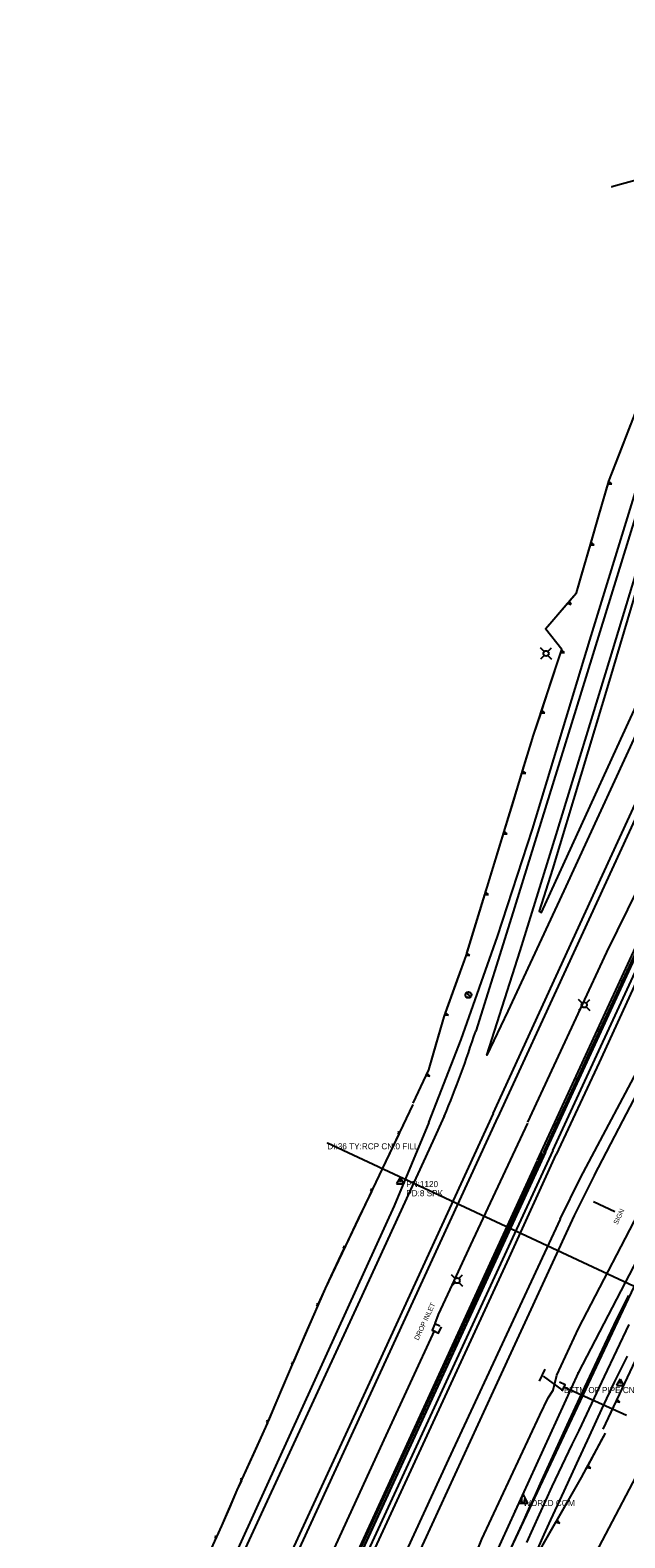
# Model space of a CAD drawing. Extents: x 978516 to 993312, y 1836504 to 1846212.
# Drawn here: x 980417 to 980904, y 1840451 to 1841686 of the extents above; entities that cross this region are included whole.
import ezdxf

# ---------------------------------------------------------------- set-up
doc = ezdxf.new("R2010")
doc.units = 0
for name, color, linetype in [('R_MOT Stage 1 Widening', 7, 'Continuous'), ('S_BASELINE', 7, 'Continuous'), ('S_CROSS_DRAIN', 7, 'Continuous'), ('S_CROSS_DRAIN_ANNOT', 7, 'Continuous'), ('S_DRG_PT_SYM', 7, 'Continuous'), ('S_DROP_INLET', 7, 'Continuous'), ('S_DROP_INLET_ANNOT', 7, 'Continuous'), ('S_EDGE_PAVEMENT', 7, 'Continuous'), ('S_FENCE', 7, 'Continuous'), ('S_HEADWALL', 7, 'Continuous'), ('S_MISC_STRUCTURES', 7, 'Continuous'), ('S_PAVEMENT_CROWN', 7, 'Continuous'), ('S_SANITARY_SEWER', 7, 'Continuous'), ('S_SECONDARY_CTL', 7, 'Continuous'), ('S_SECONDARY_CTL_ANNOT', 7, 'Continuous'), ('S_SHOULDER', 7, 'Continuous'), ('S_SIGN', 7, 'Continuous'), ('S_SIGN_ANNOT', 7, 'Continuous'), ('S_STREAM', 7, 'Continuous'), ('S_TREE', 7, 'Continuous'), ('S_UNDERGROUND_CABLE', 7, 'Continuous'), ('S_UTILITY_POLE', 7, 'Continuous'), ('S_UTILITY_POLE_ANNOT', 7, 'Continuous'), ('S_UTL_PT_SYM', 7, 'Continuous')]:
    doc.layers.add(name, color=color, linetype=linetype)

msp = doc.modelspace()

# ---------------------------------------------------------------- linework, layer by layer
at = {"layer": 'R_MOT Stage 1 Widening'}
msp.add_line((981449.8, 1841520.7), (980710.3, 1840116.9), dxfattribs=at)
at = {"layer": 'S_BASELINE'}
msp.add_line((980563.3, 1839916.3), (980929, 1840693.9), dxfattribs=at)
at = {"layer": 'S_CROSS_DRAIN'}
for p, q in [((981670.3, 1841767.9), (980893.4, 1841557.7)), ((981010.9, 1840610.6), (980660.5, 1840774.4)), ((980905.5, 1840551.6), (980854.1, 1840574.8))]:
    msp.add_line(p, q, dxfattribs=at)
at = {"layer": 'S_DRG_PT_SYM'}
for points in [[(980893.4, 1841557.7), (980893.4, 1841557.7), (980893.4, 1841557.7), (980893.4, 1841557.7), (980893.4, 1841557.7), (980893.4, 1841557.6), (980893.4, 1841557.7), (980893.5, 1841557.7)], [(980660.5, 1840774.4), (980660.5, 1840774.5), (980660.5, 1840774.4), (980660.5, 1840774.4), (980660.5, 1840774.4), (980660.5, 1840774.4), (980660.5, 1840774.4), (980660.6, 1840774.4)], [(980854.1, 1840574.8), (980854.1, 1840574.9), (980854.1, 1840574.8), (980854, 1840574.8), (980854.1, 1840574.8), (980854.1, 1840574.8), (980854.1, 1840574.8), (980854.1, 1840574.8)]]:
    msp.add_lwpolyline(points, dxfattribs=at)
at = {"layer": 'S_DROP_INLET'}
msp.add_lwpolyline([(980752.6, 1840624.6), (980748.6, 1840626.4), (980746.3, 1840621.4), (980751.5, 1840618.9), (980753.8, 1840624.1)], dxfattribs=at)
at = {"layer": 'S_EDGE_PAVEMENT'}
for points in [[(981003.8, 1841586), (980971.6, 1841480.7), (980921.6, 1841316.8), (980863.8, 1841129.5), (980811.1, 1840959.6), (980782, 1840866.2)], [(981106.5, 1841528.7), (981088, 1841488.6), (981015.6, 1841331.7), (980924.3, 1841133.4), (980854.2, 1840981), (980808.2, 1840882.6), (980791.1, 1840846.5), (980818.4, 1840932), (980847.7, 1841026.9), (980892.4, 1841172.2), (980941.7, 1841334.9), (981014.4, 1841572.8)], [(980796.3, 1840798.9), (980885.8, 1840994), (980983.5, 1841206.2), (981066.6, 1841386.4), (981127.4, 1841517.9)], [(981184.7, 1841496.4), (981112.4, 1841339.5), (981025.6, 1841150.3), (980952.7, 1840992.2), (980883, 1840840.4), (980847.7, 1840765.2)], [(980851.2, 1840712.3), (980867.8, 1840746.2), (980923.2, 1840850.4), (980998.5, 1840980.7), (981063.5, 1841091.8), (981158.1, 1841253.2), (981246.3, 1841402.8), (981274, 1841449.9)], [(980796.3, 1840798.9), (980696.5, 1840582), (980575.8, 1840319.9), (980465.8, 1840080)], [(980426.4, 1840071.6), (980466.2, 1840166.9), (980544, 1840335.5), (980687.3, 1840645.9), (980747.1, 1840776), (980756.3, 1840796.5)], [(980518.1, 1840050.1), (980634.6, 1840302.1), (980711, 1840467.7), (980809.2, 1840680.7), (980847.7, 1840765.2)], [(980851.2, 1840712.3), (980759.6, 1840515.7), (980663.5, 1840307), (980582.4, 1840130.9), (980540.6, 1840039.6)], [(980805.3, 1840430.6), (980814.9, 1840451.4), (980820.2, 1840463.1), (980825.5, 1840474.9), (980830.8, 1840486.6), (980836.1, 1840498.3), (980846.4, 1840520.9), (980856.8, 1840543.5), (980867.1, 1840565.8), (980877.5, 1840588.1), (980887.7, 1840609.5), (980897.8, 1840630.9), (980907.2, 1840649.6)], [(980832.7, 1840442.2), (980838.1, 1840454), (980843.5, 1840465.9), (980848.9, 1840477.7), (980854.3, 1840489.5), (980864.7, 1840512.1), (980875.1, 1840534.6), (980885.3, 1840556.7), (980895.6, 1840578.8), (980906.1, 1840600.1)]]:
    msp.add_lwpolyline(points, dxfattribs=at)
msp.add_ellipse((980562.9, 1840901.9), major_axis=(162.8, 433.1), ratio=0.472367, start_param=4.646, end_param=4.806827, dxfattribs=at)
at = {"layer": 'S_FENCE'}
for p, q in [((980900.7, 1840905.3), (980902.9, 1840907.4)), ((980901.7, 1840904.8), (980901.9, 1840907.9)), ((980882.2, 1840865.4), (980884.4, 1840867.5)), ((980883.2, 1840864.9), (980883.4, 1840868)), ((980863.8, 1840825.4), (980866, 1840827.5)), ((980864.8, 1840824.9), (980865, 1840828)), ((980845.4, 1840785.5), (980847.6, 1840787.6)), ((980846.4, 1840784.9), (980846.6, 1840788.1)), ((980819.2, 1840728.1), (980820.6, 1840730.6)), ((980819.4, 1840728), (980820.4, 1840730.7)), ((980800.8, 1840688.2), (980802.2, 1840690.6)), ((980801, 1840688), (980802, 1840690.8)), ((980782.3, 1840648.2), (980783.7, 1840650.7)), ((980782.5, 1840648.1), (980783.5, 1840650.8)), ((980763.9, 1840608.3), (980765.3, 1840610.7)), ((980764.1, 1840608.1), (980765.1, 1840610.9)), ((980745.5, 1840568.3), (980746.9, 1840570.8)), ((980745.7, 1840568.2), (980746.7, 1840570.9)), ((980727, 1840528.4), (980728.4, 1840530.8)), ((980727.2, 1840528.2), (980728.2, 1840531)), ((980708.6, 1840488.4), (980710, 1840490.9)), ((980708.8, 1840488.3), (980709.8, 1840491))]:
    msp.add_line(p, q, dxfattribs=at)
for points in [[(980837.3, 1840766.5), (980949, 1841008.8), (981030.5, 1841186.7), (981097.8, 1841332.7), (981154.5, 1841455.6)], [(980902.6, 1840908.2), (980911, 1840926.4)], [(980892.6, 1840886.4), (980900.9, 1840904.6)], [(980884.2, 1840868.2), (980892.6, 1840886.4)], [(980874.1, 1840846.4), (980882.5, 1840864.6)], [(980865.8, 1840828.3), (980874.1, 1840846.4)], [(980855.7, 1840806.5), (980864.1, 1840824.7)], [(980847.3, 1840788.3), (980855.7, 1840806.5)], [(980837.3, 1840766.5), (980845.6, 1840784.7)], [(980497.5, 1840030), (980690.5, 1840448.9), (980837, 1840766.4)], [(980829.1, 1840749.3), (980837, 1840766.4)], [(980820.8, 1840731.2), (980829.1, 1840749.3)], [(980810.7, 1840709.4), (980819.1, 1840727.5)], [(980802.3, 1840691.2), (980810.7, 1840709.4)], [(980792.3, 1840669.4), (980800.6, 1840687.6)], [(980783.9, 1840651.3), (980792.3, 1840669.4)], [(980773.8, 1840629.5), (980782.2, 1840647.6)], [(980765.4, 1840611.3), (980773.8, 1840629.5)], [(980755.4, 1840589.5), (980763.8, 1840607.7)], [(980747, 1840571.4), (980755.4, 1840589.5)], [(980737, 1840549.6), (980745.3, 1840567.7)], [(980728.6, 1840531.4), (980737, 1840549.6)], [(980718.5, 1840509.6), (980726.9, 1840527.8)], [(980710.1, 1840491.5), (980718.5, 1840509.6)], [(980700.1, 1840469.7), (980708.5, 1840487.8)], [(980691.7, 1840451.5), (980700.1, 1840469.7)]]:
    msp.add_lwpolyline(points, dxfattribs=at)
at = {"layer": 'S_HEADWALL'}
for points in [[(980834.1, 1840579.5), (980838.7, 1840589.4)], [(980852.8, 1840571.4), (980855.1, 1840576.6), (980850.5, 1840578.8)]]:
    msp.add_lwpolyline(points, dxfattribs=at)
at = {"layer": 'S_MISC_STRUCTURES'}
for points in [[(980839.1, 1840767.1), (981003, 1841122.8), (981098.1, 1841329.4), (981134.4, 1841407.3), (981157.1, 1841455.3), (981153.1, 1841457.4), (981097.5, 1841337), (981013.7, 1841154), (980881.3, 1840867.3), (980832.3, 1840760.5)], [(980832.2, 1840760.3), (980652.9, 1840370), (980494.9, 1840028.6)], [(980500.9, 1840033.1), (980708.6, 1840483.5), (980839.1, 1840767.1), (980839, 1840767.1), (980647, 1840349.4), (980499.2, 1840029.2)]]:
    msp.add_lwpolyline(points, dxfattribs=at)
at = {"layer": 'S_PAVEMENT_CROWN'}
msp.add_lwpolyline([(980823.9, 1840447.6), (980829.1, 1840459), (980834.2, 1840470.5), (980839.4, 1840481.9), (980844.5, 1840493.4), (980850, 1840504.8), (980855.5, 1840516.2), (980861, 1840527.6), (980866.5, 1840539.1), (980876.9, 1840561.3), (980887.3, 1840583.5), (980897.4, 1840604.8), (980907.6, 1840626.1)], dxfattribs=at)
at = {"layer": 'S_SANITARY_SEWER'}
for p, q in [((980949.2, 1840747.1), (980865.8, 1840586.5)), ((980865.8, 1840586.5), (980814.1, 1840473.3)), ((980814.1, 1840473.3), (980730.7, 1840290.2))]:
    msp.add_line(p, q, dxfattribs=at)
at = {"layer": 'S_SECONDARY_CTL'}
for p, q in [((980720.1, 1840746.1), (980717.1, 1840741.2)), ((980717.1, 1840741.2), (980723, 1840741.2)), ((980720.1, 1840746.1), (980723, 1840741.2)), ((980900.1, 1840581.1), (980897.1, 1840576.1)), ((980897.1, 1840576.1), (980903, 1840576.1)), ((980900.1, 1840581.1), (980903, 1840576.1))]:
    msp.add_line(p, q, dxfattribs=at)
for centre, radius in [((980720.1, 1840743.5), 0.311), ((980720.1, 1840743.5), 0.183), ((980720.1, 1840743.5), 0.103), ((980900.1, 1840578.5), 0.311), ((980900.1, 1840578.5), 0.183), ((980900.1, 1840578.5), 0.103)]:
    msp.add_circle(centre, radius, dxfattribs=at)
at = {"layer": 'S_SHOULDER'}
for points in [[(981020.1, 1841576.9), (980960.7, 1841383.6), (980935.5, 1841301.6), (980891.2, 1841152.8), (980844.7, 1840998.9), (980833.9, 1840964.4), (980835.7, 1840963.5), (980900.8, 1841105.2), (980961, 1841236.4), (981052.1, 1841434.2), (981098.7, 1841534.3)], [(980743.6, 1840791.3), (980770.1, 1840859.3), (980799.9, 1840943.6), (980828.4, 1841031.5), (980875.3, 1841186.3), (980935.8, 1841383.1), (980982.7, 1841537.3)], [(981133, 1841518.8), (981021.6, 1841276.6), (980931.1, 1841080.4), (980857.4, 1840920.2), (980799.8, 1840795.3)], [(980845.2, 1840768.5), (980928.9, 1840949.9), (981026.5, 1841161.7), (981122.3, 1841369.8), (981172.2, 1841479.4)], [(981279.6, 1841447.9), (981085.8, 1841116), (980988.3, 1840949), (980938, 1840861.5), (980902.1, 1840792.8), (980878.9, 1840748.3)], [(980743.6, 1840791.3), (980715.2, 1840723.1), (980668.5, 1840620.9), (980580.1, 1840426.8), (980489.8, 1840231.2), (980455.2, 1840155.4), (980417.2, 1840072.8)], [(980468.8, 1840075.4), (980639.4, 1840446.1), (980752.8, 1840692.8), (980800.2, 1840796)], [(980845.2, 1840768.5), (980731.5, 1840522.4), (980574.1, 1840181.3), (980513.8, 1840051.2)], [(980548.5, 1840031.9), (980677.2, 1840312), (980796.5, 1840571.3), (980862.9, 1840715.2), (980879.6, 1840749)]]:
    msp.add_lwpolyline(points, dxfattribs=at)
at = {"layer": 'S_SIGN'}
msp.add_lwpolyline([(980895.8, 1840718.3), (980878.3, 1840726.4)], dxfattribs=at)
msp.add_circle((980776, 1840895.9), 2.49, dxfattribs=at)
for centre, radius, start, end in [((980776.1, 1840897.1), 0.95, 16.5258, 156.8957), ((980776.7, 1840897.2), 1.5, 167.1196, 241.9813), ((980775.6, 1840894.5), 1.4, 358.6529, 73.7063), ((980775.9, 1840895), 1.28, 204.641, 335.359)]:
    msp.add_arc(centre, radius, start, end, dxfattribs=at)
at = {"layer": 'S_STREAM'}
for points in [[(980824.7, 1840791.7), (980889.3, 1840930.9), (980915.2, 1840983.7)], [(980824.3, 1840790.8), (980777.8, 1840691.2), (980760.8, 1840654.6), (980751.2, 1840634.1), (980748.5, 1840626.8)], [(980705.2, 1840264.9), (980744.1, 1840346.6), (980773.3, 1840415.8), (980787, 1840450.1), (980834.4, 1840551.8), (980841.2, 1840566), (980845.4, 1840572.2), (980848.3, 1840584.4), (980866, 1840622.6), (980922, 1840730.3)], [(980748.3, 1840621.3), (980708.5, 1840535), (980664.4, 1840439.2), (980626.5, 1840357.9), (980577.4, 1840252.8), (980527.9, 1840140.9), (980451.4, 1839975.2)], [(980837.2, 1840583.8), (980852.4, 1840572.5)]]:
    msp.add_lwpolyline(points, dxfattribs=at)
at = {"layer": 'S_TREE'}
for p, q in [((980893.4, 1841314.5), (980890.9, 1841316.3)), ((980890.3, 1841314.4), (980893.4, 1841314.5)), ((980878.9, 1841264.5), (980876.4, 1841266.4)), ((980875.8, 1841264.5), (980878.9, 1841264.5)), ((980857.2, 1841216.8), (980860.1, 1841215.6)), ((980860.1, 1841215.6), (980858.5, 1841218.3)), ((980851.6, 1841176.3), (980854.7, 1841176.3)), ((980854.7, 1841176.3), (980852.2, 1841178.2)), ((980835.4, 1841126.9), (980838.5, 1841126.9)), ((980838.5, 1841126.9), (980836, 1841128.8)), ((980819.8, 1841077.4), (980822.9, 1841077.4)), ((980822.9, 1841077.4), (980820.3, 1841079.3)), ((980804.6, 1841027.7), (980807.7, 1841027.8)), ((980807.7, 1841027.8), (980805.1, 1841029.6)), ((980789.3, 1840978), (980792.4, 1840978.1)), ((980792.4, 1840978.1), (980789.9, 1840979.9)), ((980774.1, 1840928.4), (980777.2, 1840928.4)), ((980777.2, 1840928.4), (980774.6, 1840930.2)), ((980756.5, 1840879.5), (980759.6, 1840879.4)), ((980759.6, 1840879.4), (980757.2, 1840881.3)), ((980741.4, 1840829.8), (980744.5, 1840829.4)), ((980744.5, 1840829.4), (980742.2, 1840831.6)), ((980719.8, 1840783.7), (980718.3, 1840783.3)), ((980718.3, 1840783.3), (980718.9, 1840781.9)), ((980697.4, 1840736.8), (980695.9, 1840736.4)), ((980695.9, 1840736.4), (980696.5, 1840735)), ((980675, 1840689.9), (980673.5, 1840689.5)), ((980673.5, 1840689.5), (980674.1, 1840688.1)), ((980653.1, 1840642.8), (980651.6, 1840642.3)), ((980651.6, 1840642.3), (980652.3, 1840641)), ((980632.6, 1840595), (980631.1, 1840594.6)), ((980631.1, 1840594.6), (980631.8, 1840593.2)), ((980896.9, 1840562.9), (980900, 1840562.5)), ((980900, 1840562.5), (980897.7, 1840564.7)), ((980612.2, 1840547.3), (980610.7, 1840546.8)), ((980610.7, 1840546.8), (980611.4, 1840545.4)), ((980873, 1840508.9), (980876.1, 1840508.3)), ((980876.1, 1840508.3), (980874, 1840510.6)), ((980590.9, 1840499.9), (980589.4, 1840499.4)), ((980589.4, 1840499.4), (980590.1, 1840498.1)), ((980847.6, 1840464.1), (980850.7, 1840463.4)), ((980850.7, 1840463.4), (980848.6, 1840465.8)), ((980569.9, 1840452.6), (980568.4, 1840452.1)), ((980568.4, 1840452.1), (980569.1, 1840450.8))]:
    msp.add_line(p, q, dxfattribs=at)
for points in [[(980730.7, 1840807.2), (980743.5, 1840834.4), (980756, 1840878), (980774, 1840928), (980791.2, 1840984.2), (980829.3, 1841108.5), (980852.4, 1841178.7), (980839, 1841195.6), (980864.4, 1841225.2), (980890.9, 1841316.5), (980928.7, 1841414.1), (980957.3, 1841511.3), (980972, 1841558.3)], [(980899.9, 1841339.6), (980908.9, 1841362.9)], [(980890.9, 1841316.3), (980890.9, 1841316.5), (980899.9, 1841339.6)], [(980883.3, 1841290.4), (980890.3, 1841314.4)], [(980876.4, 1841266.4), (980883.3, 1841290.4)], [(980868.9, 1841240.5), (980875.8, 1841264.5)], [(980858.5, 1841218.3), (980864.4, 1841225.2), (980868.9, 1841240.5)], [(980840.9, 1841197.8), (980857.2, 1841216.8)], [(980852.2, 1841178.2), (980852.4, 1841178.7), (980839, 1841195.6), (980840.9, 1841197.8)], [(980843.8, 1841152.6), (980851.6, 1841176.3)], [(980836, 1841128.8), (980843.8, 1841152.6)], [(980827.7, 1841103.2), (980829.3, 1841108.5), (980835.4, 1841126.9)], [(980820.3, 1841079.3), (980827.7, 1841103.2)], [(980812.5, 1841053.5), (980819.8, 1841077.4)], [(980805.1, 1841029.6), (980812.5, 1841053.5)], [(980797.2, 1841003.8), (980804.6, 1841027.7)], [(980789.9, 1840979.9), (980791.2, 1840984.2), (980797.2, 1841003.8)], [(980886.2, 1840540.3), (980961.4, 1840699.8), (980994.3, 1840749.1), (981040, 1840829.6), (981098.3, 1840928.6), (981121.2, 1840967.9), (981130.5, 1840975.5), (981171.8, 1840993.3), (981172, 1840993.4)], [(980782, 1840954.1), (980789.3, 1840978)], [(980774.6, 1840930.2), (980782, 1840954.1)], [(980765.6, 1840904.8), (980774, 1840928), (980774.1, 1840928.4)], [(980757.2, 1840881.3), (980765.6, 1840904.8)], [(980749.5, 1840855.5), (980756, 1840878), (980756.5, 1840879.5)], [(980742.2, 1840831.6), (980743.5, 1840834.4), (980749.5, 1840855.5)], [(980730.7, 1840807.2), (980741.4, 1840829.8)], [(980730.6, 1840806.2), (980658.6, 1840655.6), (980632.3, 1840594.6), (980609.9, 1840541.9), (980586.5, 1840490.2), (980573.8, 1840461.1), (980543, 1840393.4), (980524.3, 1840353.4), (980499.7, 1840298.6), (980480.4, 1840239.8)], [(980730.6, 1840806.2), (980719.8, 1840783.7)], [(980718.9, 1840781.9), (980708.2, 1840759.3)], [(980708.2, 1840759.3), (980697.4, 1840736.8)], [(980696.5, 1840735), (980685.8, 1840712.4)], [(980685.8, 1840712.4), (980675, 1840689.9)], [(980674.1, 1840688.1), (980663.3, 1840665.6)], [(980663.3, 1840665.6), (980658.6, 1840655.6), (980653.1, 1840642.8)], [(980652.3, 1840641), (980642.4, 1840618)], [(980642.4, 1840618), (980632.6, 1840595)], [(980631.8, 1840593.2), (980622, 1840570.2)], [(980897.7, 1840564.7), (980908.3, 1840587.2)], [(980622, 1840570.2), (980612.2, 1840547.3)], [(980886.2, 1840540.3), (980896.9, 1840562.9)], [(980611.4, 1840545.4), (980609.9, 1840541.9), (980601.2, 1840522.6)], [(980822.8, 1840330.6), (980809.5, 1840333.2), (980797.2, 1840340.9), (980796.7, 1840364.2), (980807.9, 1840389.2), (980822.1, 1840419.7), (980868.6, 1840500.7), (980888.3, 1840537.1)], [(980874, 1840510.6), (980885.5, 1840532)], [(980885.5, 1840532), (980888.3, 1840537.1)], [(980601.2, 1840522.6), (980590.9, 1840499.9)], [(980861, 1840487.4), (980868.6, 1840500.7), (980873, 1840508.9)], [(980590.1, 1840498.1), (980586.5, 1840490.2), (980580, 1840475.3)], [(980848.6, 1840465.8), (980861, 1840487.4)], [(980580, 1840475.3), (980573.8, 1840461.1), (980569.9, 1840452.6)], [(980835.2, 1840442.5), (980847.6, 1840464.1)]]:
    msp.add_lwpolyline(points, dxfattribs=at)
at = {"layer": 'S_UNDERGROUND_CABLE'}
for p, q in [((980820.8, 1840486.8), (980817.3, 1840479.7)), ((980817.3, 1840479.7), (980824.3, 1840479.7)), ((980819.6, 1840480.9), (980819.6, 1840483.4)), ((980820.2, 1840480.3), (980819.6, 1840480.9)), ((980821.4, 1840480.3), (980820.2, 1840480.3)), ((980820.8, 1840486.8), (980824.3, 1840479.7)), ((980822, 1840480.9), (980821.4, 1840480.3)), ((980822, 1840483.4), (980822, 1840480.9))]:
    msp.add_line(p, q, dxfattribs=at)
at = {"layer": 'S_UTILITY_POLE'}
for p, q in [((980837.9, 1841177), (980834.9, 1841180)), ((980841.1, 1841177), (980844.1, 1841180)), ((980837.9, 1841173.9), (980834.9, 1841170.9)), ((980841.1, 1841173.9), (980844.1, 1841170.9)), ((980869.2, 1840889.2), (980866.2, 1840892.2)), ((980869.2, 1840886.1), (980866.2, 1840883.1)), ((980872.4, 1840889.2), (980875.4, 1840892.2)), ((980872.4, 1840886.1), (980875.4, 1840883.1)), ((980765.1, 1840663.6), (980762.1, 1840666.6)), ((980768.2, 1840663.6), (980771.2, 1840666.6)), ((980765.1, 1840660.4), (980762.1, 1840657.4)), ((980768.2, 1840660.4), (980771.2, 1840657.4))]:
    msp.add_line(p, q, dxfattribs=at)
for centre in [(980839.5, 1841175.5), (980870.8, 1840887.7), (980766.7, 1840662)]:
    msp.add_circle(centre, 2.21, dxfattribs=at)
at = {"layer": 'S_UTL_PT_SYM'}
for points in [[(980865.8, 1840586.5), (980865.8, 1840586.6), (980865.8, 1840586.5), (980865.8, 1840586.5), (980865.8, 1840586.5), (980865.8, 1840586.5), (980865.8, 1840586.5), (980865.9, 1840586.5)], [(980865.8, 1840586.5), (980865.8, 1840586.6), (980865.8, 1840586.5), (980865.8, 1840586.5), (980865.8, 1840586.5), (980865.8, 1840586.5), (980865.8, 1840586.5), (980865.9, 1840586.5)], [(980814.1, 1840473.3), (980814.1, 1840473.3), (980814.1, 1840473.3), (980814, 1840473.3), (980814.1, 1840473.3), (980814.1, 1840473.2), (980814.1, 1840473.3), (980814.1, 1840473.3)], [(980814.1, 1840473.3), (980814.1, 1840473.3), (980814.1, 1840473.3), (980814, 1840473.3), (980814.1, 1840473.3), (980814.1, 1840473.2), (980814.1, 1840473.3), (980814.1, 1840473.3)]]:
    msp.add_lwpolyline(points, dxfattribs=at)

# ---------------------------------------------------------------- texts
at = {"layer": 'S_CROSS_DRAIN_ANNOT'}
for s, p in [('DI:36 TY:RCP CN:0 FILL', (980660.5, 1840769.4)), ('BTTM OF PIPE CN:0%FILL', (980854.1, 1840569.8))]:
    msp.add_text(s, height=5, dxfattribs=at).set_placement(p)
at = {"layer": 'S_DROP_INLET_ANNOT'}
msp.add_text('DROP INLET', height=4, rotation=64.9823, dxfattribs=at).set_placement((980735, 1840612.7))
at = {"layer": 'S_SECONDARY_CTL'}
for p in [(980718.9, 1840741.5), (980898.9, 1840576.5)]:
    msp.add_text('TV', height=1.5, dxfattribs=at).set_placement(p)
at = {"layer": 'S_SECONDARY_CTL_ANNOT'}
for s, p in [('PN:1120', (980725.1, 1840738.5)), ('PD:8 SPK', (980725.1, 1840731))]:
    msp.add_text(s, height=5, dxfattribs=at).set_placement(p)
at = {"layer": 'S_SIGN_ANNOT'}
msp.add_text('SIGN', height=4, rotation=64.6953, dxfattribs=at).set_placement((980898, 1840707.4))
at = {"layer": 'S_UTILITY_POLE_ANNOT'}
msp.add_text('WORLD COM', height=5, dxfattribs=at).set_placement((980820.8, 1840477.3))

doc.saveas('drawing.dxf')
